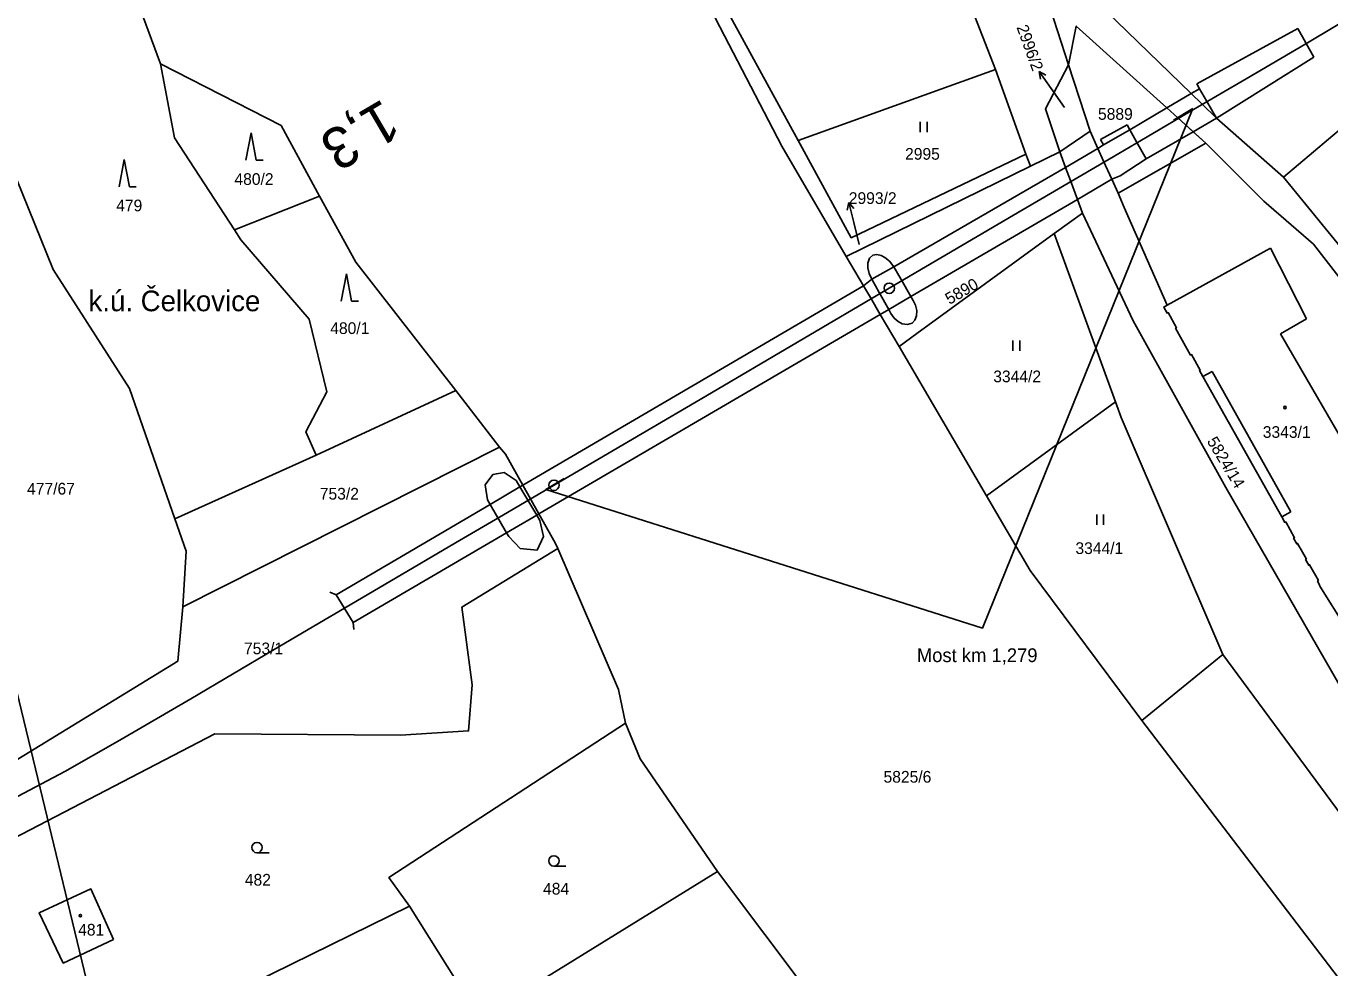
# Model space of a CAD drawing. Extents: x -738085 to -734306, y -1122197 to -1119753.
# Drawn here: x -735309.7 to -735120.1, y -1120386.3 to -1120249.4 of the extents above; entities that cross this region are included whole.
import ezdxf

# ---------------------------------------------------------------- set-up
doc = ezdxf.new("R2010")
doc.units = 0
for name, color, linetype in [('Hranice parcel', 7, 'Continuous'), ('Parcelní čísla', 7, 'Continuous'), ('Pop  PČ popisy', 7, 'Continuous'), ('Popis PS-SO', 7, 'Continuous'), ('SŽDC', 7, 'Continuous'), ('Vnitřní kresba', 7, 'Continuous'), ('Vrstva 1', 7, 'Continuous'), ('Vrstva 53', 7, 'Continuous'), ('Vrstva 7', 7, 'Continuous'), ('Značky budov', 7, 'Continuous'), ('Značky kultur', 7, 'Continuous')]:
    doc.layers.add(name, color=color, linetype=linetype)

msp = doc.modelspace()

# ---------------------------------------------------------------- linework, layer by layer
at = {"layer": 'Hranice parcel'}
for p, q in [((-735164.65, -1120234.85), (-735158.13, -1120255.05)), ((-735168.74, -1120255.72), (-735172.55, -1120246.06)), ((-735288.13, -1120265.67), (-735290.18, -1120254.92)), ((-735272.61, -1120263.87), (-735290.18, -1120254.92)), ((-735272.61, -1120263.87), (-735290.18, -1120254.92)), ((-735158.13, -1120255.05), (-735155.01, -1120264.72)), ((-735168.74, -1120255.72), (-735197.46, -1120266.06)), ((-735164.35, -1120268.03), (-735168.74, -1120255.72)), ((-735115.98, -1120262.16), (-735126.91, -1120271.38)), ((-735267.06, -1120274.13), (-735272.61, -1120263.87)), ((-735267.06, -1120274.13), (-735272.61, -1120263.87)), ((-735279.42, -1120279.02), (-735288.13, -1120265.67)), ((-735159.43, -1120267.72), (-735155.01, -1120264.72)), ((-735138.19, -1120266.43), (-735150.92, -1120273.72)), ((-735163.66, -1120269.79), (-735164.35, -1120268.03)), ((-735159.43, -1120267.72), (-735163.66, -1120269.79)), ((-735190.45, -1120282.92), (-735163.66, -1120269.79)), ((-735267.06, -1120274.13), (-735279.42, -1120279.02)), ((-735160.23, -1120279.59), (-735156.12, -1120276.6)), ((-735151.32, -1120304.02), (-735160.23, -1120279.59)), ((-735170.08, -1120317.68), (-735182.79, -1120296)), ((-735294.69, -1120302.11), (-735288.06, -1120321.06)), ((-735267.54, -1120311.77), (-735247.23, -1120302.41)), ((-735240.86, -1120310.61), (-735247.23, -1120302.41)), ((-735240.86, -1120310.61), (-735247.23, -1120302.41)), ((-735151.32, -1120304.02), (-735170.08, -1120317.68)), ((-735288.06, -1120321.06), (-735267.54, -1120311.77)), ((-735286.9, -1120333.84), (-735240.86, -1120310.61)), ((-735288.06, -1120321.06), (-735286.41, -1120325.76)), ((-735286.41, -1120325.76), (-735286.9, -1120333.84)), ((-735147.48, -1120350.36), (-735135.71, -1120340.76)), ((-735243.71, -1120393.6), (-735209.2, -1120372.29)), ((-735192.01, -1120395.09), (-735209.2, -1120372.29)), ((-735192.01, -1120395.09), (-735209.2, -1120372.29)), ((-735253.96, -1120377.31), (-735243.71, -1120393.6))]:
    msp.add_line(p, q, dxfattribs=at)
for points in [[(-735290.18, -1120254.92), (-735317.57, -1120180.85), (-735339.79, -1120142.5), (-735361.49, -1120104.8), (-735379.62, -1120073.45), (-735392.28, -1120051.31)], [(-735290.18, -1120254.92), (-735317.57, -1120180.85), (-735339.79, -1120142.5), (-735361.49, -1120104.8), (-735379.62, -1120073.45), (-735392.28, -1120051.31)], [(-735197.46, -1120266.06), (-735209.83, -1120243.45), (-735214.81, -1120230.09)], [(-735190.45, -1120282.92), (-735199.82, -1120266.86), (-735209.49, -1120248.33), (-735217.93, -1120231.25)], [(-735323.36, -1120244.09), (-735313.82, -1120265.06), (-735305.75, -1120284.8), (-735294.69, -1120302.11)], [(-735126.91, -1120271.38), (-735136.63, -1120262.8), (-735138.78, -1120260.72), (-735140.3, -1120259.25), (-735154.27, -1120245.72)], [(-735158.13, -1120255.05), (-735157.02, -1120249.44), (-735143.85, -1120261.32), (-735142.27, -1120262.75), (-735140.02, -1120264.78), (-735138.19, -1120266.43)], [(-735159.43, -1120267.72), (-735161.48, -1120261.45), (-735158.13, -1120255.05)], [(-735164.35, -1120268.03), (-735189.73, -1120280.19), (-735197.46, -1120266.06)], [(-735155.01, -1120264.72), (-735153.88, -1120267.2), (-735153.04, -1120269.05), (-735151.85, -1120271.68), (-735150.92, -1120273.72)], [(-735138.19, -1120266.43), (-735129.75, -1120274.85), (-735122.53, -1120281.1), (-735108.15, -1120299.66), (-735094.95, -1120315.79)], [(-735156.12, -1120276.6), (-735156.86, -1120274.61), (-735157.88, -1120271.88), (-735158.59, -1120269.96), (-735159.43, -1120267.72)], [(-735099.51, -1120304.86), (-735120.4, -1120279.32), (-735126.91, -1120271.38)], [(-735150.92, -1120273.72), (-735150.07, -1120275.8), (-735143.82, -1120290), (-735144.31, -1120290.27), (-735143.82, -1120291.14), (-735143.68, -1120291.06), (-735142.44, -1120293.26), (-735142.58, -1120293.34), (-735140.39, -1120297.25), (-735140.26, -1120297.17), (-735138.99, -1120299.43), (-735139.12, -1120299.5), (-735138.63, -1120300.37), (-735127.15, -1120320.77), (-735126.7, -1120321.57), (-735126.57, -1120321.49), (-735125.29, -1120323.79), (-735125.42, -1120323.86), (-735124.96, -1120324.69), (-735124.83, -1120324.61), (-735124.12, -1120325.87), (-735123.55, -1120326.9), (-735123.68, -1120326.97), (-735123.23, -1120327.78), (-735123.09, -1120327.71), (-735121.81, -1120330), (-735121.94, -1120330.08), (-735121.68, -1120330.54), (-735121.6, -1120330.83), (-735117.78, -1120336.94)], [(-735247.23, -1120302.41), (-735261.74, -1120283.75), (-735267.06, -1120274.13)], [(-735247.23, -1120302.41), (-735261.74, -1120283.75), (-735267.06, -1120274.13)], [(-735107.92, -1120352.48), (-735113.07, -1120355.6), (-735113.62, -1120354.14), (-735135.26, -1120316.47), (-735148.73, -1120292.25), (-735156.12, -1120276.6)], [(-735267.54, -1120311.77), (-735269.05, -1120308.41), (-735266, -1120302.56), (-735268.53, -1120292.03), (-735278.46, -1120280.49), (-735279.42, -1120279.02)], [(-735160.23, -1120279.59), (-735180.2, -1120294.12), (-735182.79, -1120296)], [(-735182.79, -1120296), (-735185.51, -1120291.35), (-735186.95, -1120288.89), (-735187.96, -1120287.16), (-735190.45, -1120282.92)], [(-735135.71, -1120340.76), (-735150.47, -1120306.33), (-735151.32, -1120304.02)], [(-735232.39, -1120325.34), (-735232.79, -1120324.54), (-735235.15, -1120320.33), (-735236.32, -1120318.24), (-735237.48, -1120316.17), (-735240.01, -1120311.65), (-735240.86, -1120310.61)], [(-735232.39, -1120325.34), (-735232.79, -1120324.54), (-735235.15, -1120320.33), (-735236.32, -1120318.24), (-735237.48, -1120316.17), (-735240.01, -1120311.65), (-735240.86, -1120310.61)], [(-735147.48, -1120350.36), (-735163.71, -1120328.57), (-735170.08, -1120317.68)], [(-735232.39, -1120325.34), (-735246.33, -1120333.87), (-735244.86, -1120345.18), (-735245.36, -1120351.86), (-735255.28, -1120352.46), (-735282.27, -1120352.3), (-735312.75, -1120368.12)], [(-735222.54, -1120350.71), (-735223.57, -1120345.84), (-735232.39, -1120325.34)], [(-735222.54, -1120350.71), (-735223.57, -1120345.84), (-735232.39, -1120325.34)], [(-735286.9, -1120333.84), (-735287.65, -1120341.7), (-735311.53, -1120356.35), (-735349.49, -1120373.13), (-735376.69, -1120383.59)], [(-735040.76, -1120465.73), (-735061.72, -1120440.92), (-735081.14, -1120416.75), (-735107.98, -1120378.29), (-735135.71, -1120340.76)], [(-735253.96, -1120377.31), (-735256.94, -1120373.18), (-735222.54, -1120350.71)], [(-735209.2, -1120372.29), (-735220.41, -1120355.94), (-735222.54, -1120350.71)], [(-735209.2, -1120372.29), (-735220.41, -1120355.94), (-735222.54, -1120350.71)], [(-735147.48, -1120350.36), (-735112.36, -1120396.34), (-735065.9, -1120453.92), (-735050.6, -1120469.95)], [(-735296.97, -1120382.18), (-735304.29, -1120385.59), (-735307.78, -1120378.28), (-735300.27, -1120374.83), (-735296.97, -1120382.18)], [(-735282.89, -1120413.25), (-735294.07, -1120397.05), (-735253.96, -1120377.31)]]:
    msp.add_lwpolyline(points, dxfattribs=at)
at = {"layer": 'Pop  PČ popisy'}
for p, q in [((-735160.68, -1120258.5), (-735162.4, -1120256.04)), ((-735162.4, -1120256.04), (-735161.42, -1120256.57)), ((-735162.4, -1120256.04), (-735162.24, -1120257.15)), ((-735158.74, -1120261.27), (-735160.68, -1120258.5)), ((-735190.1, -1120275.07), (-735190.34, -1120276.16)), ((-735189.37, -1120277.98), (-735190.1, -1120275.07)), ((-735190.1, -1120275.07), (-735189.37, -1120275.92)), ((-735188.57, -1120281.18), (-735189.37, -1120277.98))]:
    msp.add_line(p, q, dxfattribs=at)
at = {"layer": 'Popis PS-SO'}
for points in [[(-735140.07, -1120261.43), (-735170.66, -1120336.92), (-735234.13, -1120316.77), (-735231.46, -1120315.2)], [(-735142.89, -1120263.09), (-735140.07, -1120261.43)]]:
    msp.add_lwpolyline(points, dxfattribs=at)
at = {"layer": 'SŽDC'}
for p, q in [((-735154.27, -1120245.72), (-735140.3, -1120259.25)), ((-735140.3, -1120259.25), (-735138.78, -1120260.72)), ((-735138.78, -1120260.72), (-735136.63, -1120262.8)), ((-735126.91, -1120271.38), (-735115.98, -1120262.16)), ((-735136.63, -1120262.8), (-735126.91, -1120271.38)), ((-735240.86, -1120310.61), (-735286.9, -1120333.84))]:
    msp.add_line(p, q, dxfattribs=at)
for points in [[(-735232.39, -1120325.34), (-735232.79, -1120324.54), (-735235.15, -1120320.33), (-735236.32, -1120318.24), (-735237.48, -1120316.17), (-735240.01, -1120311.65), (-735240.86, -1120310.61)], [(-735312.75, -1120368.12), (-735282.27, -1120352.3), (-735255.28, -1120352.46), (-735245.36, -1120351.86), (-735244.86, -1120345.18), (-735246.33, -1120333.87), (-735232.39, -1120325.34)], [(-735286.9, -1120333.84), (-735287.65, -1120341.7), (-735311.53, -1120356.35), (-735349.49, -1120373.13), (-735376.69, -1120383.59)]]:
    msp.add_lwpolyline(points, dxfattribs=at)
at = {"layer": 'Vnitřní kresba'}
for p, q in [((-735139.47, -1120257.84), (-735124.82, -1120249.79)), ((-735124.82, -1120249.79), (-735123.66, -1120251.88)), ((-735123.66, -1120251.88), (-735122.5, -1120253.95)), ((-735136.63, -1120262.8), (-735122.5, -1120253.95)), ((-735140.3, -1120259.25), (-735139.08, -1120258.53)), ((-735139.47, -1120257.84), (-735139.08, -1120258.53)), ((-735139.08, -1120258.53), (-735138.06, -1120260.3)), ((-735143.85, -1120261.32), (-735140.3, -1120259.25)), ((-735138.06, -1120260.3), (-735136.63, -1120262.8)), ((-735149.25, -1120264.49), (-735143.85, -1120261.32)), ((-735153.48, -1120265.89), (-735149.64, -1120263.79)), ((-735153.04, -1120266.71), (-735149.25, -1120264.49)), ((-735149.64, -1120263.79), (-735149.25, -1120264.49)), ((-735149.25, -1120264.49), (-735148.26, -1120266.26)), ((-735140.02, -1120264.78), (-735136.63, -1120262.8)), ((-735153.48, -1120265.89), (-735153.04, -1120266.71)), ((-735148.26, -1120266.26), (-735146.88, -1120268.74)), ((-735146.88, -1120268.74), (-735140.02, -1120264.78)), ((-735158.59, -1120269.96), (-735153.88, -1120267.2)), ((-735153.88, -1120267.2), (-735153.04, -1120266.71)), ((-735183.56, -1120284.42), (-735158.59, -1120269.96)), ((-735150.64, -1120271.17), (-735146.88, -1120268.74)), ((-735156.86, -1120274.61), (-735151.85, -1120271.68)), ((-735151.85, -1120271.68), (-735150.64, -1120271.17)), ((-735181.05, -1120288.74), (-735156.86, -1120274.61)), ((-735187.34, -1120283.88), (-735187.08, -1120283.15)), ((-735187.08, -1120283.15), (-735186.58, -1120282.73)), ((-735186.58, -1120282.73), (-735185.99, -1120282.64)), ((-735185.99, -1120282.64), (-735185.39, -1120282.76)), ((-735185.39, -1120282.76), (-735184.84, -1120283.04)), ((-735184.84, -1120283.04), (-735184.19, -1120283.57)), ((-735143.82, -1120290), (-735128.76, -1120281.7)), ((-735128.76, -1120281.7), (-735123.55, -1120291.98)), ((-735187.34, -1120284.58), (-735187.34, -1120283.88)), ((-735187.34, -1120284.58), (-735187.14, -1120285.4)), ((-735187.14, -1120285.4), (-735186.76, -1120286.23)), ((-735186.76, -1120286.23), (-735183.56, -1120284.42)), ((-735184.19, -1120283.57), (-735183.56, -1120284.42)), ((-735183.56, -1120284.42), (-735182.48, -1120286.28)), ((-735237.48, -1120316.17), (-735187.96, -1120287.16)), ((-735187.96, -1120287.16), (-735186.76, -1120286.23)), ((-735186.76, -1120286.23), (-735185.68, -1120288.15)), ((-735182.48, -1120286.28), (-735181.05, -1120288.74)), ((-735185.68, -1120288.15), (-735184.29, -1120290.63)), ((-735184.29, -1120290.63), (-735181.05, -1120288.74)), ((-735181.05, -1120288.74), (-735180.71, -1120289.32)), ((-735185.51, -1120291.35), (-735184.29, -1120290.63)), ((-735184.29, -1120290.63), (-735183.97, -1120291.2)), ((-735180.71, -1120289.32), (-735180.4, -1120289.97)), ((-735180.4, -1120289.97), (-735180.22, -1120290.76)), ((-735180.24, -1120291.55), (-735180.22, -1120290.76)), ((-735235.15, -1120320.33), (-735185.51, -1120291.35)), ((-735183.97, -1120291.2), (-735183.49, -1120291.86)), ((-735183.49, -1120291.86), (-735182.93, -1120292.37)), ((-735182.93, -1120292.37), (-735182.34, -1120292.69)), ((-735182.34, -1120292.69), (-735181.56, -1120292.79)), ((-735181.56, -1120292.79), (-735180.9, -1120292.59)), ((-735180.9, -1120292.59), (-735180.48, -1120292.16)), ((-735180.48, -1120292.16), (-735180.24, -1120291.55)), ((-735127.32, -1120294.17), (-735123.55, -1120291.98)), ((-735127.32, -1120294.17), (-735115.57, -1120314.42)), ((-735138.63, -1120300.37), (-735137.28, -1120299.61)), ((-735137.28, -1120299.61), (-735125.8, -1120320.01)), ((-735242.95, -1120316.09), (-735241.86, -1120314.62)), ((-735241.86, -1120314.62), (-735240.2, -1120314.29)), ((-735240.2, -1120314.29), (-735238.45, -1120315.48)), ((-735238.45, -1120315.48), (-735237.9, -1120316.41)), ((-735242.62, -1120318.29), (-735242.95, -1120316.09)), ((-735242.23, -1120318.96), (-735237.9, -1120316.41)), ((-735237.9, -1120316.41), (-735237.48, -1120316.17)), ((-735237.9, -1120316.41), (-735235.46, -1120320.51)), ((-735264.63, -1120332.08), (-735242.23, -1120318.96)), ((-735242.23, -1120318.96), (-735242.62, -1120318.29)), ((-735239.84, -1120323.07), (-735242.23, -1120318.96)), ((-735239.84, -1120323.07), (-735235.46, -1120320.51)), ((-735235.46, -1120320.51), (-735235.15, -1120320.33)), ((-735235.46, -1120320.51), (-735235.01, -1120321.27)), ((-735235.01, -1120321.27), (-735234.49, -1120323.6)), ((-735127.15, -1120320.77), (-735125.8, -1120320.01)), ((-735262.15, -1120336.1), (-735239.84, -1120323.07)), ((-735239.54, -1120323.59), (-735239.84, -1120323.07)), ((-735237.89, -1120325.33), (-735239.54, -1120323.59)), ((-735234.49, -1120323.6), (-735235.38, -1120325.58)), ((-735235.38, -1120325.58), (-735237.89, -1120325.33)), ((-735265.55, -1120331.69), (-735264.63, -1120332.08)), ((-735264.63, -1120332.08), (-735262.15, -1120336.1)), ((-735262.06, -1120337.1), (-735262.15, -1120336.1))]:
    msp.add_line(p, q, dxfattribs=at)
at = {"layer": 'Vrstva 1'}
msp.add_lwpolyline([(-734541.63, -1119996.45), (-735348.44, -1120191.3), (-735283.42, -1120460.56), (-734476.61, -1120265.71)], close=True, dxfattribs=at)
for points in [[(-735048.63, -1120207.9), (-735071.26, -1120221.19), (-735095.02, -1120235.15), (-735119.18, -1120249.35), (-735123.66, -1120251.99), (-735132.32, -1120257.08), (-735139.95, -1120261.55), (-735146.73, -1120265.54), (-735150.83, -1120267.95), (-735166.13, -1120276.92), (-735184.2, -1120287.53), (-735210.89, -1120303.2), (-735238.62, -1120319.49), (-735239.7, -1120320.12), (-735247.26, -1120324.55), (-735256.8, -1120330.14), (-735273.62, -1120340.02), (-735285.77, -1120347.18), (-735296.08, -1120353.22), (-735304.06, -1120357.75)], [(-735304.06, -1120357.75), (-735312.6, -1120362.28)]]:
    msp.add_lwpolyline(points, dxfattribs=at)
at = {"layer": 'Vrstva 53'}
for points in [[(-734742.39, -1120198.31), (-734748.46, -1120195.41), (-734799.69, -1120183.7), (-734853.28, -1120170.95), (-734887.03, -1120164.91), (-734913.87, -1120162.91), (-734932.65, -1120163.73), (-734954.75, -1120168.56), (-734977.62, -1120176.17), (-734996.5, -1120184.52), (-735013.84, -1120194.15), (-735022.76, -1120201.89), (-735069.62, -1120231.25), (-735085.17, -1120235.61), (-735095.46, -1120241.5), (-735115.98, -1120262.16), (-735126.91, -1120271.38), (-735136.63, -1120262.8), (-735138.78, -1120260.72), (-735140.3, -1120259.25), (-735154.27, -1120245.72)], [(-735150.92, -1120273.72), (-735151.85, -1120271.68), (-735153.04, -1120269.05), (-735153.88, -1120267.2), (-735155.01, -1120264.72), (-735158.13, -1120255.05), (-735157.02, -1120249.44), (-735143.85, -1120261.32), (-735142.27, -1120262.75), (-735138.19, -1120266.43), (-735150.92, -1120273.72)], [(-735190.45, -1120282.92), (-735163.66, -1120269.79), (-735159.43, -1120267.72), (-735158.59, -1120269.96), (-735157.88, -1120271.88), (-735156.86, -1120274.61), (-735156.12, -1120276.6), (-735160.23, -1120279.59), (-735180.2, -1120294.12), (-735182.79, -1120296), (-735185.51, -1120291.35), (-735186.95, -1120288.89), (-735187.96, -1120287.16), (-735190.45, -1120282.92)], [(-735476.81, -1120520.24), (-735469.07, -1120485.97), (-735464.3, -1120469.55), (-735452.33, -1120447.02), (-735446.3, -1120439.84), (-735427.81, -1120417.92), (-735417.02, -1120407.52), (-735410.34, -1120401.13), (-735404.44, -1120397.94), (-735404, -1120397.71), (-735389.72, -1120390.04), (-735385.37, -1120387.89), (-735376.69, -1120383.59), (-735349.49, -1120373.13), (-735311.53, -1120356.35), (-735287.63, -1120341.7), (-735286.9, -1120333.84), (-735286.41, -1120325.76), (-735288.06, -1120321.06), (-735267.54, -1120311.77), (-735247.23, -1120302.41)], [(-735247.23, -1120302.41), (-735240.86, -1120310.61), (-735240.01, -1120311.65), (-735237.48, -1120316.17), (-735236.32, -1120318.24), (-735235.15, -1120320.33), (-735232.79, -1120324.54), (-735232.39, -1120325.34)], [(-735232.39, -1120325.34), (-735246.33, -1120333.87), (-735244.86, -1120345.18), (-735245.38, -1120351.86), (-735255.28, -1120352.46), (-735282.27, -1120352.3), (-735312.75, -1120368.12), (-735322.23, -1120372.05), (-735346.89, -1120382.27), (-735362.63, -1120388.07), (-735366.38, -1120391.25), (-735378.33, -1120401.35), (-735382.4, -1120409.22), (-735402.62, -1120422.52), (-735415.17, -1120433.19), (-735415.72, -1120433.76), (-735429.56, -1120448.26), (-735438.13, -1120462.62), (-735446.24, -1120476.88), (-735453.74, -1120491.74), (-735463.45, -1120520.42), (-735461.09, -1120521.79), (-735476.81, -1120520.24)]]:
    msp.add_lwpolyline(points, dxfattribs=at)
at = {"layer": 'Vrstva 7'}
for centre in [(-735184.2, -1120287.53), (-735232.95, -1120316.16)]:
    msp.add_circle(centre, 0.75, dxfattribs=at)
at = {"layer": 'Značky budov'}
for centre in [(-735126.69, -1120304.86), (-735301.81, -1120378.71)]:
    msp.add_circle(centre, 0.175, dxfattribs=at)
at = {"layer": 'Značky kultur'}
for p, q in [((-735179.69, -1120264.84), (-735179.69, -1120263.34)), ((-735178.69, -1120264.84), (-735178.69, -1120263.34)), ((-735277, -1120264.92), (-735277.75, -1120268.92)), ((-735276.25, -1120268.92), (-735277, -1120264.92)), ((-735295.42, -1120268.8), (-735296.17, -1120272.8)), ((-735294.67, -1120272.8), (-735295.42, -1120268.8)), ((-735276.25, -1120268.92), (-735275.25, -1120268.92)), ((-735294.67, -1120272.8), (-735293.68, -1120272.8)), ((-735263.12, -1120285.41), (-735263.87, -1120289.41)), ((-735262.37, -1120289.41), (-735263.12, -1120285.41)), ((-735262.37, -1120289.41), (-735261.37, -1120289.41)), ((-735166.24, -1120296.63), (-735166.24, -1120295.13)), ((-735165.24, -1120296.63), (-735165.24, -1120295.13)), ((-735154.05, -1120321.93), (-735154.05, -1120320.43)), ((-735153.05, -1120321.93), (-735153.05, -1120320.43)), ((-735276.13, -1120369.57), (-735274.38, -1120369.57)), ((-735232.96, -1120371.51), (-735231.21, -1120371.51))]:
    msp.add_line(p, q, dxfattribs=at)
for centre in [(-735276.13, -1120368.82), (-735232.96, -1120370.76)]:
    msp.add_circle(centre, 0.75, dxfattribs=at)

# ---------------------------------------------------------------- texts
at = {"layer": 'Hranice parcel'}
msp.add_text('k.ú. Čelkovice', height=3, dxfattribs=at).set_placement((-735300.62, -1120290.87))
at = {"layer": 'Parcelní čísla'}
for s, rotation, p in [('2996/2', 290, (-735165.73, -1120249.59)), ('5890', 30, (-735175.45, -1120289.96)), ('5824/14', 301, (-735138.09, -1120309.75))]:
    msp.add_text(s, height=1.7, rotation=rotation, dxfattribs=at).set_placement(p)
for s, p in [('5889', (-735153.86, -1120263.05)), ('2995', (-735181.91, -1120268.85)), ('480/2', (-735279.41, -1120272.51)), ('2993/2', (-735190.09, -1120275.28)), ('479', (-735296.6, -1120276.35)), ('480/1', (-735265.48, -1120294.18)), ('3344/2', (-735169.09, -1120301.19)), ('3343/1', (-735129.9, -1120309.27)), ('477/67', (-735309.56, -1120317.51)), ('753/2', (-735267, -1120318.24)), ('3344/1', (-735157.14, -1120326.15)), ('753/1', (-735278.02, -1120340.72)), ('5825/6', (-735185.04, -1120359.38)), ('482', (-735277.9, -1120374.34)), ('484', (-735234.54, -1120375.64)), ('481', (-735302.13, -1120381.6))]:
    msp.add_text(s, height=1.7, dxfattribs=at).set_placement(p)
at = {"layer": 'Popis PS-SO'}
msp.add_text('Most km 1,279', height=2, dxfattribs=at).set_placement((-735180.19, -1120341.86))
at = {"layer": 'Vrstva 7'}
msp.add_text('1,3', height=6, rotation=210.4253, dxfattribs=at).set_placement((-735257.8, -1120259.91))

doc.saveas('drawing.dxf')
